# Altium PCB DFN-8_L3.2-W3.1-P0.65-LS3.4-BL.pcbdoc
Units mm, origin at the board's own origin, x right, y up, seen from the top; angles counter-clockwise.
Board outline 15.91 x 16.48 mm, 2 copper layers (Top Layer, Bottom Layer), stack 0 mm thick; 1 components, 0 nets, 9 pads, 0 vias.
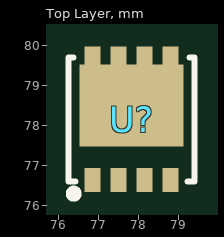
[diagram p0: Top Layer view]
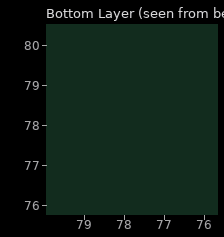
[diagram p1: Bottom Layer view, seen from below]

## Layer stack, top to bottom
Top Layer: signal copper (thickness not stored)
Bottom Layer: signal copper (thickness not stored)

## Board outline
85.761,69.85 69.85,69.85 69.85,86.33 85.761,86.33

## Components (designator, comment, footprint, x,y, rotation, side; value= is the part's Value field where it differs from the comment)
U? "" DFN-8_L3.2-W3.1-P0.65-LS3.4-BL 77.835,78.16 r0 top

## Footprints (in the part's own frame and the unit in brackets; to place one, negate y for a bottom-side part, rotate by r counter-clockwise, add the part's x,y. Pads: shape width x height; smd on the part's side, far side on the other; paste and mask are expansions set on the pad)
DFN-8_L3.2-W3.1-P0.65-LS3.4-BL [mm]
  rect 0.4x0.6 smd paste-100 mask+0.051: 1(-0.975,-1.52) 2(-0.325,-1.52) 3(0.325,-1.52) 4(0.975,-1.52) 5(0.975,1.52) 6(0.325,1.52) 7(-0.325,1.52) 8(-0.975,1.52)
  rect 2.6x2.05 smd paste-100 mask+0.051: 9(0,0.35)
  silkscreen extent -1.58,-1.96 1.58,1.55

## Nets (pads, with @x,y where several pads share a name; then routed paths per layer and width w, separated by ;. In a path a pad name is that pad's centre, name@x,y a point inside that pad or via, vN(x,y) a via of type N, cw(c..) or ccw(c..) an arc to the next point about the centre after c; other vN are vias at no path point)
pads on no net: U?.1 U?.2 U?.3 U?.4 U?.5 U?.6 U?.7 U?.8 U?.9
